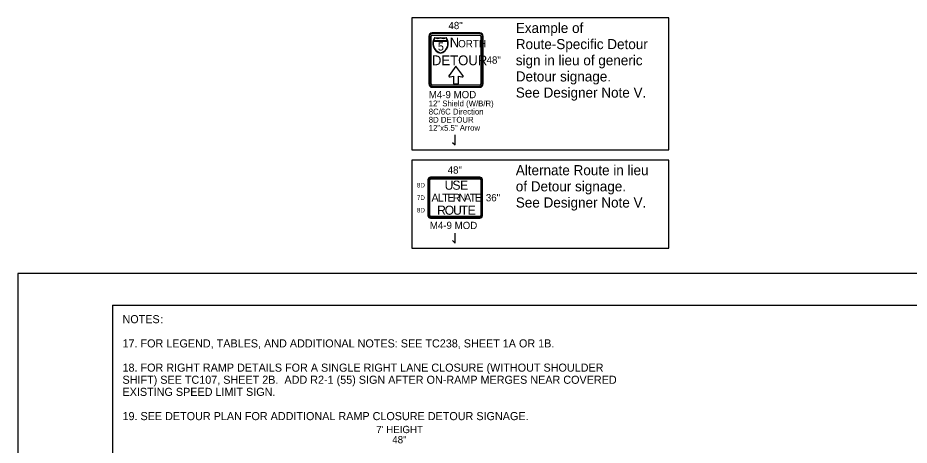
# Model space of a CAD drawing. Extents: x 99999 to 100116, y 99995 to 100013.
# Drawn here: x 100059.06 to 100067.9, y 100008.99 to 100013.22 of the extents above; entities that cross this region are included whole.
import ezdxf

# ---------------------------------------------------------------- set-up
doc = ezdxf.new("R2010")
doc.units = 0
for name, color, linetype in [('SH_GI_GeneralNotesBodyText', 7, 'Continuous'), ('SH_GI_PlotLimits', 7, 'Continuous'), ('SH_GI_SheetBorder', 7, 'Continuous'), ('TR_SN_ConstructionSigns', 7, 'Continuous'), ('TR_WZ_WorkZoneDetails', 7, 'Continuous')]:
    doc.layers.add(name, color=color, linetype=linetype)

msp = doc.modelspace()

# ---------------------------------------------------------------- linework, layer by layer
at = {"layer": 'SH_GI_PlotLimits'}
msp.add_lwpolyline([(100059.0625, 99999.6875), (100076.0625, 99999.6875), (100076.0625, 100010.6875), (100059.0625, 100010.6875)], close=True, dxfattribs=at)
at = {"layer": 'SH_GI_SheetBorder'}
for q in [(100060, 100000), (100075.75, 100010.375)]:
    msp.add_line((100060, 100010.375), q, dxfattribs=at)
at = {"layer": 'TR_SN_ConstructionSigns'}
for p, q in [((100063.1354, 100013.0373), (100063.1354, 100012.5648)), ((100063.1438, 100013.0373), (100063.1438, 100012.5648)), ((100063.1579, 100012.5648), (100063.1579, 100013.0373)), ((100063.6416, 100013.0711), (100063.1691, 100013.0711)), ((100063.6416, 100013.0626), (100063.1691, 100013.0626)), ((100063.1691, 100013.0486), (100063.6416, 100013.0486)), ((100063.6529, 100013.0373), (100063.6529, 100012.5648)), ((100063.6669, 100012.5648), (100063.6669, 100013.0373)), ((100063.6754, 100012.5648), (100063.6754, 100013.0373)), ((100063.3228, 100012.9875), (100063.1823, 100012.9875)), ((100063.1823, 100012.9875), (100063.3228, 100012.9875)), ((100063.1834, 100012.9912), (100063.3217, 100012.9912)), ((100063.3217, 100012.9912), (100063.1834, 100012.9912)), ((100063.6416, 100012.5536), (100063.1691, 100012.5536)), ((100063.1691, 100012.5395), (100063.6416, 100012.5395)), ((100063.1691, 100012.5311), (100063.6416, 100012.5311)), ((100063.6424, 100011.6405), (100063.153, 100011.6405)), ((100063.6424, 100011.6335), (100063.153, 100011.6335)), ((100063.153, 100011.6236), (100063.6424, 100011.6236)), ((100063.1277, 100011.6152), (100063.1277, 100011.2608)), ((100063.1347, 100011.6152), (100063.1347, 100011.2608)), ((100063.1446, 100011.2608), (100063.1446, 100011.6152)), ((100063.6508, 100011.6152), (100063.6508, 100011.2608)), ((100063.6607, 100011.2608), (100063.6607, 100011.6152)), ((100063.6677, 100011.2608), (100063.6677, 100011.6152)), ((100063.6424, 100011.2524), (100063.153, 100011.2524)), ((100063.153, 100011.2425), (100063.6424, 100011.2425)), ((100063.153, 100011.2355), (100063.6424, 100011.2355))]:
    msp.add_line(p, q, dxfattribs=at)
msp.add_lwpolyline([(100063.3367, 100012.6494), (100063.3356, 100012.6478), (100063.335, 100012.6461), (100063.3347, 100012.6441), (100063.3348, 100012.6424), (100063.335, 100012.6412), (100063.3356, 100012.6398), (100063.3373, 100012.6375), (100063.3386, 100012.6364), (100063.34, 100012.6355), (100063.3417, 100012.6348), (100063.3432, 100012.6345), (100063.3447, 100012.6343), (100063.3465, 100012.6343), (100063.3478, 100012.6346), (100063.3795, 100012.6424), (100063.3795, 100012.5671), (100063.4307, 100012.5671), (100063.4307, 100012.6429), (100063.4617, 100012.6337), (100063.4647, 100012.6331), (100063.4681, 100012.6334), (100063.4703, 100012.6342), (100063.4733, 100012.6362), (100063.4752, 100012.6389), (100063.476, 100012.6414), (100063.4761, 100012.6436), (100063.4754, 100012.6463), (100063.4746, 100012.6477), (100063.4051, 100012.7405), (100063.3367, 100012.6494)], dxfattribs=at)
for centre, radius, start, end in [((100063.1691, 100013.0373), 0.0337, 90, 180), ((100063.1691, 100013.0373), 0.0253, 90, 180), ((100063.1691, 100013.0373), 0.0113, 90, 180), ((100063.6416, 100013.0373), 0.0338, 360, 90), ((100063.6416, 100013.0373), 0.0253, 360, 90), ((100063.6416, 100013.0373), 0.0113, 360, 90), ((100063.2725, 100012.9642), 0.0973, 142.16169, 258.18105), ((100063.2715, 100012.9633), 0.0925, 164.85517, 258.18105), ((100063.2715, 100012.9633), 0.0925, 164.85517, 258.18105), ((100063.2715, 100012.9633), 0.0925, 142.16169, 162.48397), ((100063.2715, 100012.9633), 0.0925, 142.16169, 162.48397), ((100063.2245, 100013.1212), 0.1014, 253.48525, 286.04538), ((100063.2259, 100013.1124), 0.0964, 253.48525, 286.04538), ((100063.2259, 100013.1124), 0.0964, 253.48525, 286.04538), ((100063.2806, 100013.1212), 0.1014, 253.95462, 286.51475), ((100063.2792, 100013.1124), 0.0964, 253.95462, 286.51475), ((100063.2792, 100013.1124), 0.0964, 253.95462, 286.51475), ((100063.2325, 100012.9642), 0.0974, 281.90384, 37.84925), ((100063.2335, 100012.9633), 0.0925, 281.90384, 15.1558), ((100063.2335, 100012.9633), 0.0925, 281.90384, 15.1558), ((100063.2335, 100012.9633), 0.0925, 17.52691, 37.84925), ((100063.2335, 100012.9633), 0.0925, 17.52691, 37.84925), ((100063.1691, 100012.5648), 0.0338, 180, 270), ((100063.1691, 100012.5648), 0.0253, 180, 270), ((100063.1691, 100012.5648), 0.0113, 180, 270), ((100063.6416, 100012.5648), 0.0337, 270, 360), ((100063.6416, 100012.5648), 0.0253, 270, 0), ((100063.6416, 100012.5648), 0.0113, 270, 0), ((100063.153, 100011.6152), 0.0253, 90, 180), ((100063.153, 100011.6152), 0.0183, 90, 180), ((100063.153, 100011.6152), 0.00844, 90, 180), ((100063.6424, 100011.6152), 0.0253, 360, 90), ((100063.6424, 100011.6152), 0.0183, 360, 90), ((100063.6424, 100011.6152), 0.00844, 360, 90), ((100063.153, 100011.2608), 0.0253, 180, 270), ((100063.153, 100011.2608), 0.0183, 180, 270), ((100063.153, 100011.2608), 0.00844, 180, 270), ((100063.6424, 100011.2608), 0.0253, 270, 360), ((100063.6424, 100011.2608), 0.0183, 270, 0), ((100063.6424, 100011.2608), 0.00844, 270, 0)]:
    msp.add_arc(centre, radius, start, end, dxfattribs=at)
at = {"layer": 'TR_WZ_WorkZoneDetails'}
for p, q in [((100063.3963, 100011.9605), (100063.3963, 100012.0605)), ((100063.3713, 100011.9855), (100063.3963, 100011.9605)), ((100063.3963, 100010.9875), (100063.3963, 100011.0875)), ((100063.3713, 100011.0125), (100063.3963, 100010.9875))]:
    msp.add_line(p, q, dxfattribs=at)
for points in [[(100062.9666, 100011.9105), (100065.5143, 100011.9105), (100065.5143, 100013.2191), (100062.9666, 100013.2191)], [(100062.9666, 100010.9375), (100065.5143, 100010.9375), (100065.5143, 100011.8105), (100062.9666, 100011.8105)]]:
    msp.add_lwpolyline(points, close=True, dxfattribs=at)

# ---------------------------------------------------------------- texts
at = {"layer": 'SH_GI_GeneralNotesBodyText'}
for s, p in [('NOTES', (100060.1, 100010.195)), (':', (100060.4743, 100010.195)), ('17. FOR LEGEND, TABLES, AND ADDITIONAL NOTES: SEE TC238, SHEET 1A OR 1B.', (100060.1, 100009.955)), ('18. FOR RIGHT RAMP DETAILS FOR A SINGLE RIGHT LANE CLOSURE (WITHOUT SHOULDER ', (100060.1, 100009.715)), ('SHIFT) SEE TC107, SHEET 2B.  ADD R2-1 (55) SIGN AFTER ON-RAMP MERGES NEAR COVERED ', (100060.1, 100009.595)), ('EXISTING SPEED LIMIT SIGN.', (100060.1, 100009.475)), ('19. SEE DETOUR PLAN FOR ADDITIONAL RAMP CLOSURE DETOUR SIGNAGE.', (100060.1, 100009.235))]:
    msp.add_text(s, height=0.08, rotation=360, dxfattribs=at).set_placement(p)
at = {"layer": 'TR_SN_ConstructionSigns'}
for s, height, p in [('48"', 0.072, (100063.3306, 100013.1071)), ('5', 0.081, (100063.2253, 100012.8951)), ('N', 0.0972, (100063.3432, 100012.9267)), ('ORTH', 0.0729, (100063.4264, 100012.9267)), ('DETOUR', 0.0972, (100063.1668, 100012.7497)), ('48"', 0.072, (100063.7086, 100012.7651)), ('M4-9 MOD', 0.072, (100063.1354, 100012.4231)), ('12" Shield (W/B/R)', 0.0576, (100063.1354, 100012.3424)), ('8C/6C Direction', 0.0576, (100063.1354, 100012.2618)), ('8D DETOUR', 0.0576, (100063.1354, 100012.1811)), ('12"x5.5" Arrow', 0.0576, (100063.1354, 100012.1005)), ('48"', 0.072, (100063.323, 100011.6765)), ('36"', 0.072, (100063.7015, 100011.402)), ('M4-9 MOD', 0.072, (100063.1457, 100011.1275)), ("7' HEIGHT", 0.072, (100062.6156, 100009.1065)), ('48"', 0.072, (100062.774, 100009.0057))]:
    msp.add_text(s, height=height, rotation=360, dxfattribs=at).set_placement(p)
for s, height, p in [('8D', 0.045, (100063.018, 100011.5392)), ('U', 0.09, (100063.2933, 100011.5167)), ('S', 0.09, (100063.3698, 100011.5167)), ('E', 0.09, (100063.4463, 100011.5167)), ('7D', 0.045, (100063.018, 100011.4155)), ('A', 0.0787, (100063.1626, 100011.3986)), ('L', 0.0787, (100063.2241, 100011.3986)), ('T', 0.0787, (100063.269, 100011.3986)), ('E', 0.0787, (100063.3201, 100011.3986)), ('R', 0.0787, (100063.3737, 100011.3986)), ('N', 0.0787, (100063.4312, 100011.3986)), ('A', 0.0787, (100063.4863, 100011.3986)), ('T', 0.0787, (100063.5414, 100011.3986)), ('E', 0.0787, (100063.5926, 100011.3986)), ('R', 0.09, (100063.2186, 100011.2692)), ('O', 0.09, (100063.2933, 100011.2692)), ('U', 0.09, (100063.377, 100011.2692)), ('T', 0.09, (100063.4517, 100011.2692)), ('E', 0.09, (100063.521, 100011.2692)), ('8D', 0.045, (100063.018, 100011.2917))]:
    msp.add_text(s, height=height, dxfattribs=at).set_placement(p)
at = {"layer": 'TR_WZ_WorkZoneDetails'}
for s, p in [('Example of ', (100063.9983, 100013.0691)), ('Route-Specific Detour ', (100063.9983, 100012.9091)), ('sign in lieu of generic ', (100063.9983, 100012.7491)), ('Detour signage.', (100063.9983, 100012.5891)), ('See Designer Note V.', (100063.9983, 100012.4291)), ('Alternate Route in lieu ', (100063.9983, 100011.6605)), ('of Detour signage.', (100063.9983, 100011.5005)), ('See Designer Note V.', (100063.9983, 100011.3405))]:
    msp.add_text(s, height=0.1, dxfattribs=at).set_placement(p)

doc.saveas('drawing.dxf')
